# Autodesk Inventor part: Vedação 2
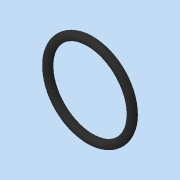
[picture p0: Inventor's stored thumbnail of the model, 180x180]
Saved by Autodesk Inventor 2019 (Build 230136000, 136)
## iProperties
Created: 2019-08
Part Number: Vedação 2
Material: Borracha
Document SubType Name: Modeling
Designer: Usuario
Density: 0.93 g/cm^3
Appearance: Borracha - Preta
Author: Usuario
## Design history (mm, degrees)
sketch "Esboço1"
  geometry: L1 (0, 1.25)-(0, -1.25); C1 r 1.25 at (13.25, 0); 1 further point
  constraints: 2 end point, 1 centre point, 1 vertical
  dimensions: "d1" = 90 deg dimension on point (0, 0) C1.centre C1 L1.start L1.end L1
revolve "Revolução1" sketch "Esboço1" stored, may be unused: angle "d1" = 90 deg
node "Sólido1"
